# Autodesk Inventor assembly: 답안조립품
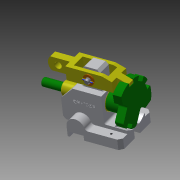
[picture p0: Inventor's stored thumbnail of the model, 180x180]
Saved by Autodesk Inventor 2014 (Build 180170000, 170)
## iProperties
Created: 2016-11
Part Number: 답안조립품
Document SubType Name: Assembly
Designer: USER
Author: USER
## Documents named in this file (8)
- C:\Users\USER\Desktop\461108V1033\답안조립품.iam
- C:\Users\USER\Desktop\461108V1033\본체.ipt
- C:\Users\USER\Desktop\461108V1033\부시.ipt
- C:\Users\USER\Desktop\461108V1033\분할대.ipt
- C:\Users\USER\Desktop\461108V1033\분할축.ipt
- C:\Users\USER\Desktop\461108V1033\와셔.ipt
- C:\Users\USER\Desktop\461108V1033\원통형핀.ipt
- C:\Users\USER\Desktop\461108V1033\클레비스핀.ipt
